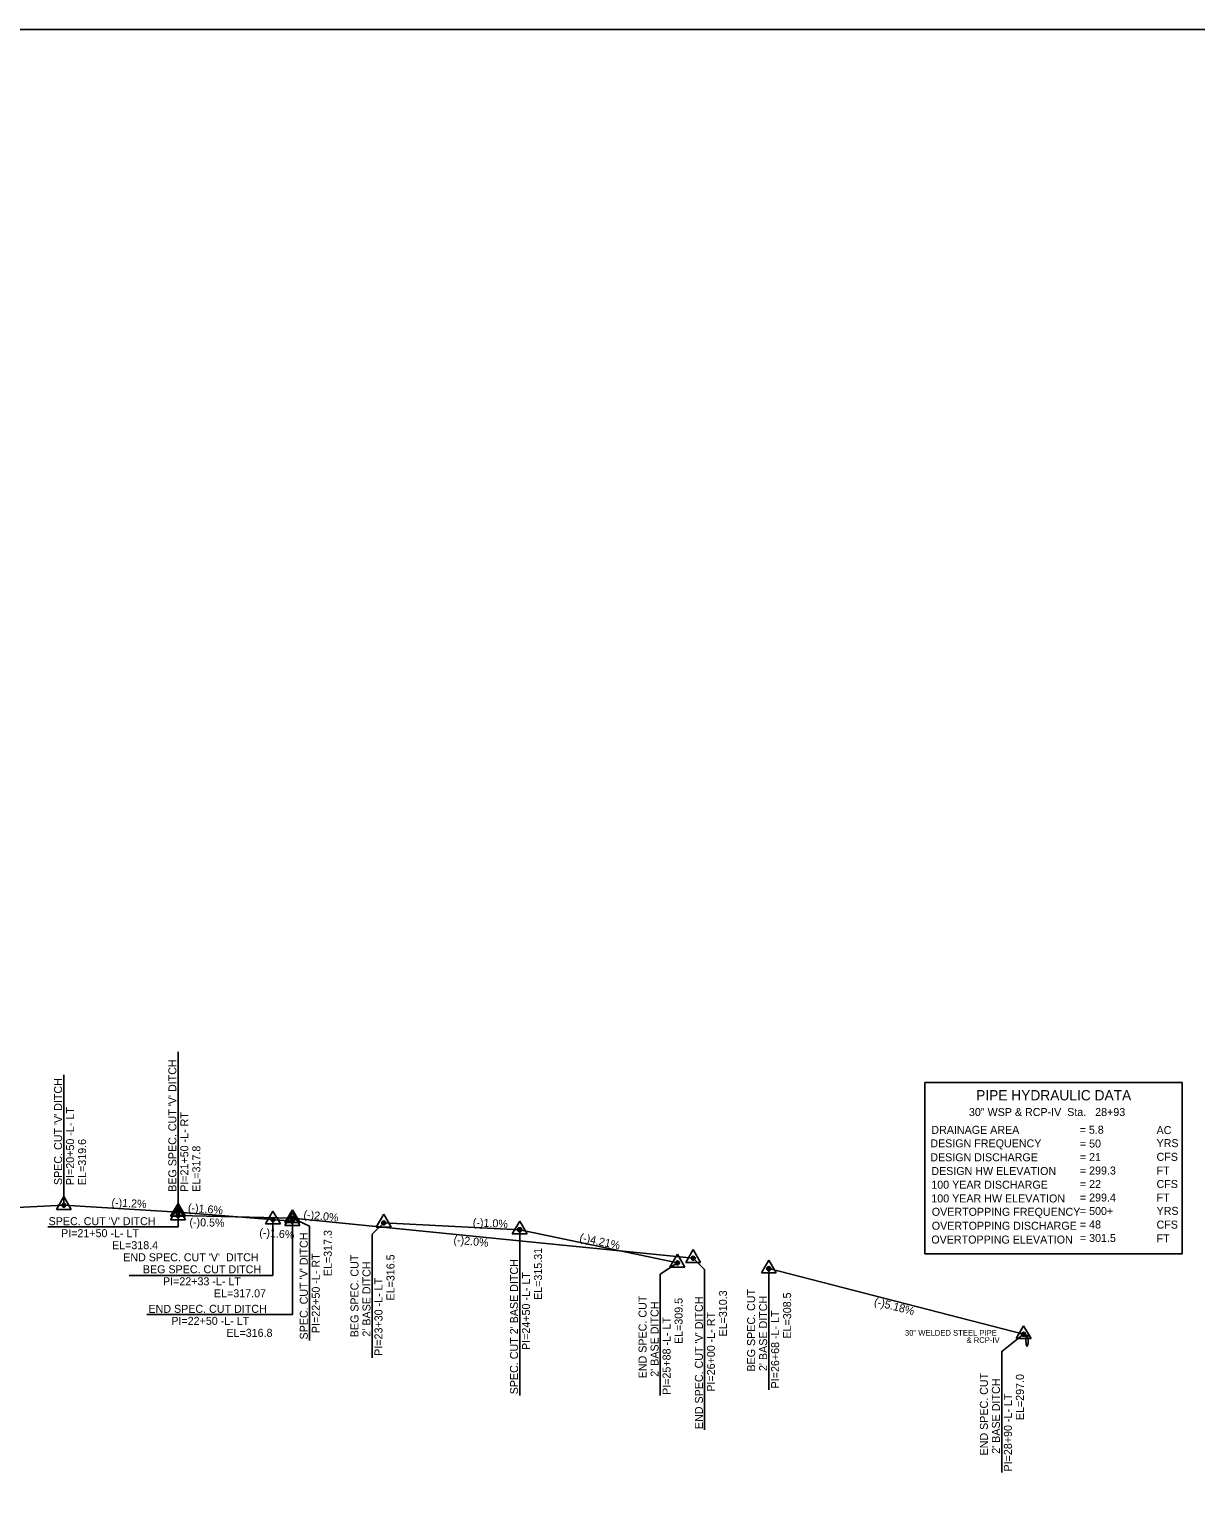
# Model space of a CAD drawing. Extents: x 2110519 to 2119088, y 667494 to 672447.
# Drawn here: x 2113747 to 2114767, y 671161 to 672447 of the extents above; entities that cross this region are included whole.
import ezdxf

# ---------------------------------------------------------------- set-up
doc = ezdxf.new("R2010")
doc.units = 0
for name, color, linetype in [('Exist Horizontal Alignment', 7, 'Continuous'), ('Old_Level_1', 7, 'Continuous'), ('Old_Level_2', 7, 'Continuous'), ('Prop Conc 1ft 6in Curb and Gutter', 7, 'Continuous'), ('Prop Conc 5in Monolithic Surface Mount Island', 7, 'Continuous'), ('Prop Conc Curb 8in x 18in', 7, 'Continuous'), ('Prop EOT', 7, 'Continuous'), ('Prop Paved Shoulder', 7, 'Continuous'), ('Scratch_Level_4', 7, 'Continuous')]:
    doc.layers.add(name, color=color, linetype=linetype)

msp = doc.modelspace()

# ---------------------------------------------------------------- linework, layer by layer
at = {"layer": 'Exist Horizontal Alignment'}
msp.add_lwpolyline([(2110519.2, 672447), (2115845.7, 672447), (2115845.7, 670168.2), (2110519.2, 670168.2)], close=True, dxfattribs=at)
at = {"layer": 'Old_Level_1'}
for p, q in [((2113776.7, 671425.7), (2113770.2, 671414.5)), ((2113776.7, 671425.7), (2113783.2, 671414.5)), ((2113876.7, 671419.7), (2113870.2, 671408.5)), ((2113876.7, 671419.7), (2113883.2, 671408.5)), ((2113770.2, 671414.5), (2113783.2, 671414.5)), ((2113870.2, 671408.5), (2113883.2, 671408.5)), ((2113959.7, 671413.1), (2113953.2, 671401.9)), ((2113959.7, 671413.1), (2113966.2, 671401.9)), ((2113959.7, 671356.7), (2113959.7, 671405.6)), ((2113976.7, 671411.7), (2113970.2, 671400.5)), ((2113976.7, 671411.7), (2113983.2, 671400.5)), ((2114056.7, 671410.2), (2114050.2, 671399)), ((2114056.7, 671410.2), (2114063.2, 671399)), ((2114175.7, 671404.2), (2114169.2, 671393)), ((2114175.7, 671404.2), (2114182.2, 671393)), ((2113953.2, 671401.9), (2113966.2, 671401.9)), ((2113970.2, 671400.5), (2113983.2, 671400.5)), ((2114050.2, 671399), (2114063.2, 671399)), ((2114169.2, 671393), (2114182.2, 671393)), ((2114175.7, 671396.7), (2114175.7, 671251.7)), ((2114313.7, 671375.2), (2114307.2, 671364)), ((2114307.2, 671364), (2114320.2, 671364)), ((2114313.7, 671375.2), (2114320.2, 671364)), ((2114393.7, 671370.2), (2114387.2, 671359)), ((2114393.7, 671370.2), (2114400.2, 671359)), ((2113833.9, 671356.7), (2113959.7, 671356.7)), ((2114387.2, 671359), (2114400.2, 671359)), ((2114393.7, 671362.7), (2114393.7, 671256.7)), ((2114616.7, 671312.7), (2114610.2, 671301.5)), ((2114616.7, 671312.7), (2114623.2, 671301.5)), ((2114610.2, 671301.5), (2114623.2, 671301.5))]:
    msp.add_line(p, q, dxfattribs=at)
for points in [[(2113776.7, 671418.2), (2113776.7, 671532.2)], [(2113876.7, 671412.2), (2113876.7, 671399.2), (2113762.7, 671399.2)], [(2113976.7, 671404.2), (2113976.7, 671322.5), (2113849.3, 671322.5)], [(2114056.7, 671402.7), (2114046.7, 671392.7), (2114046.7, 671284.7)], [(2114313.7, 671367.7), (2114298.7, 671357.7), (2114298.7, 671251.7)], [(2114616.7, 671305.2), (2114597.6, 671290.2), (2114597.6, 671184.2)]]:
    msp.add_lwpolyline(points, dxfattribs=at)
for centre, radius in [((2113776.7, 671418.2), 1.75), ((2113776.7, 671418.2), 1.2), ((2113776.7, 671418.2), 0.5), ((2113876.7, 671412.2), 1.75), ((2113876.7, 671412.2), 1.2), ((2113876.7, 671412.2), 0.5), ((2113959.7, 671405.6), 1.75), ((2113959.7, 671405.6), 1.2), ((2113959.7, 671405.6), 0.5), ((2113976.7, 671404.2), 1.75), ((2113976.7, 671404.2), 1.2), ((2113976.7, 671404.2), 0.5), ((2114056.7, 671402.7), 1.75), ((2114056.7, 671402.7), 1.2), ((2114056.7, 671402.7), 0.5), ((2114175.7, 671396.7), 1.75), ((2114175.7, 671396.7), 1.2), ((2114175.7, 671396.7), 0.5), ((2114313.7, 671367.7), 1.75), ((2114313.7, 671367.7), 1.2), ((2114313.7, 671367.7), 0.5), ((2114393.7, 671362.7), 1.75), ((2114393.7, 671362.7), 1.2), ((2114393.7, 671362.7), 0.5), ((2114616.7, 671305.2), 1.75), ((2114616.7, 671305.2), 1.2), ((2114616.7, 671305.2), 0.5)]:
    msp.add_circle(centre, radius, dxfattribs=at)
at = {"layer": 'Old_Level_2'}
for p, q in [((2113626.7, 671410.7), (2113776.7, 671418.2)), ((2114393.7, 671362.7), (2114616.7, 671305.2)), ((2114616.7, 671305.2), (2114616.7, 671305.2))]:
    msp.add_line(p, q, dxfattribs=at)
for points in [[(2113776.7, 671418.2), (2113876.7, 671412.2), (2113976.7, 671404.2)], [(2114056.7, 671402.7), (2114175.7, 671396.7), (2114313.7, 671367.7)]]:
    msp.add_lwpolyline(points, dxfattribs=at)
at = {"layer": 'Prop Conc Curb 8in x 18in'}
msp.add_lwpolyline([(2114530.3, 671375.5), (2114755.3, 671375.5), (2114755.3, 671525.5), (2114530.3, 671525.5)], close=True, dxfattribs=at)
at = {"layer": 'Prop EOT'}
msp.add_lwpolyline([(2113876.7, 671409.2), (2113976.7, 671406.7), (2114327.5, 671371.8)], dxfattribs=at)
at = {"layer": 'Prop Paved Shoulder'}
msp.add_ellipse((2114619.7, 671299.7), major_axis=(0, 5), ratio=0.2, dxfattribs=at)
at = {"layer": 'Scratch_Level_4'}
for p, q in [((2113876.7, 671409.2), (2113876.7, 671552.3)), ((2113876.7, 671416.7), (2113870.2, 671405.5)), ((2113876.7, 671416.7), (2113883.2, 671405.5)), ((2113870.2, 671405.5), (2113883.2, 671405.5)), ((2113976.7, 671414.2), (2113970.2, 671403)), ((2113970.2, 671403), (2113983.2, 671403)), ((2113976.7, 671414.2), (2113983.2, 671403)), ((2114327.5, 671379.3), (2114321, 671368.1)), ((2114327.5, 671379.3), (2114334, 671368.1)), ((2114321, 671368.1), (2114334, 671368.1))]:
    msp.add_line(p, q, dxfattribs=at)
for points in [[(2113976.7, 671406.7), (2113991.7, 671399.8), (2113991.7, 671299.8)], [(2114327.5, 671371.8), (2114337.5, 671361.8), (2114337.5, 671221.7)]]:
    msp.add_lwpolyline(points, dxfattribs=at)
for centre, radius in [((2113876.7, 671409.2), 1.75), ((2113876.7, 671409.2), 1.2), ((2113876.7, 671409.2), 0.5), ((2113976.7, 671406.7), 1.75), ((2113976.7, 671406.7), 1.2), ((2113976.7, 671406.7), 0.5), ((2114327.5, 671371.8), 1.75), ((2114327.5, 671371.8), 1.2), ((2114327.5, 671371.8), 0.5)]:
    msp.add_circle(centre, radius, dxfattribs=at)

# ---------------------------------------------------------------- texts
at = {"layer": 'Old_Level_1'}
for s, rotation, p in [("SPEC. CUT 'V' DITCH ", 90, (2113775.2, 671435.8)), ('PI=20+50 -L- LT', 90, (2113785.7, 671435.8)), ('EL=319.6', 90, (2113796.2, 671435.8)), ('(-)1.6%', 355.4261, (2113885.1, 671412.6)), ("SPEC. CUT 'V' DITCH ", 0, (2113763.4, 671400.7)), ('PI=21+50 -L- LT', 0, (2113774.3, 671390.2)), ('(-)1.6%', 355.4261, (2113947.6, 671391.1)), ('EL=318.4', 0, (2113818.9, 671379.7)), ('EL=315.31', 90, (2114195.2, 671335.3)), ("END SPEC. CUT 'V'  DITCH", 0, (2113828.7, 671369.1)), ('BEG SPEC. CUT DITCH ', 0, (2113845.9, 671358.6)), ('BEG SPEC. CUT ', 90, (2114034.6, 671302.6)), ("2' BASE DITCH ", 90, (2114045.1, 671303.2)), ('EL=316.5', 90, (2114066.1, 671334.8)), ("SPEC. CUT 2' BASE DITCH ", 90, (2114174.2, 671252.7)), ('PI=22+33 -L- LT', 0, (2113863.5, 671348.1)), ('PI=23+30 -L- LT', 90, (2114055.6, 671286.4)), ('PI=24+50 -L- LT', 90, (2114184.7, 671291.5)), ('EL=317.07', 0, (2113908.1, 671337.6)), ('END SPEC. CUT ', 90, (2114286.7, 671266.7)), ('BEG SPEC. CUT ', 90, (2114381.7, 671272.6)), ('EL=308.5', 90, (2114413.2, 671301.5)), ('END SPEC. CUT DITCH ', 0, (2113850.8, 671324)), ("2' BASE DITCH ", 90, (2114297.2, 671268.1)), ('EL=309.5', 90, (2114318.2, 671296.7)), ("2' BASE DITCH ", 90, (2114392.2, 671273.1)), ('PI=26+68 -L- LT', 90, (2114402.7, 671257.9)), ('PI=22+50 -L- LT', 0, (2113870.8, 671313.5)), ('PI=25+88 -L- LT', 90, (2114307.7, 671252.2)), ('EL=316.8', 0, (2113919, 671303)), ('END SPEC. CUT ', 90, (2114585.4, 671199.2)), ("2' BASE DITCH", 90, (2114595.9, 671200.7)), ('EL=297.0', 90, (2114616.9, 671230.1)), ('PI=28+90 -L- LT', 90, (2114606.4, 671185.2))]:
    msp.add_text(s, height=7, rotation=rotation, dxfattribs=at).set_placement(p)
at = {"layer": 'Old_Level_2'}
for s, rotation, p in [('(-)1.2%', 357.1369, (2113818.3, 671417.2)), ('(-)1.0%', 357.1136, (2114134.5, 671399.8)), ('(-)4.21%', 348.1124, (2114227.6, 671386.8)), ('(-)5.18%', 345.5534, (2114485.3, 671330.8))]:
    msp.add_text(s, height=7, rotation=rotation, dxfattribs=at).set_placement(p)
at = {"layer": 'Prop Conc 1ft 6in Curb and Gutter'}
for s, height, p in [('PIPE HYDRAULIC DATA', 9, (2114575.1, 671509.9)), ('30" WSP & RCP-IV  Sta.   28+93   ', 7, (2114568.8, 671496.2)), ('DRAINAGE AREA', 7, (2114535.9, 671480.6)), ('= 5.8    ', 7, (2114665.7, 671480.7)), ('AC', 7, (2114733, 671480.4)), ('DESIGN FREQUENCY', 7, (2114535, 671468.8)), ('= 50 ', 7, (2114665.9, 671468.6)), ('YRS', 7, (2114733, 671469)), ('DESIGN DISCHARGE', 7, (2114535, 671456.6)), ('= 21      ', 7, (2114665.9, 671456.8)), ('CFS', 7, (2114733, 671457)), ('DESIGN HW ELEVATION', 7, (2114535.9, 671444.6)), ('= 299.3   ', 7, (2114665.9, 671445)), ('FT', 7, (2114733, 671445)), ('100 YEAR DISCHARGE', 7, (2114535.9, 671432.6)), ('= 22      ', 7, (2114665.9, 671433.2)), ('= 299.4   ', 7, (2114665.9, 671421.4)), ('CFS', 7, (2114733, 671433.2)), ('FT', 7, (2114733, 671421.4)), ('100 YEAR HW ELEVATION', 7, (2114535.9, 671420.6)), ('OVERTOPPING FREQUENCY', 7, (2114536.3, 671408.9)), ('= 500+  ', 7, (2114665.9, 671409.6)), ('YRS', 7, (2114733, 671409.7)), ('OVERTOPPING DISCHARGE', 7, (2114536.3, 671396.7)), ('= 48      ', 7, (2114665.9, 671397.8)), ('CFS', 7, (2114733, 671397.7)), ('OVERTOPPING ELEVATION', 7, (2114535.9, 671384.6)), ('= 301.5   ', 7, (2114665.9, 671386)), ('FT', 7, (2114733, 671385.6))]:
    msp.add_text(s, height=height, dxfattribs=at).set_placement(p)
at = {"layer": 'Prop Conc 5in Monolithic Surface Mount Island'}
for s, p in [('30" WELDED STEEL PIPE', (2114512.8, 671304)), ('& RCP-IV', (2114566.7, 671297.7))]:
    msp.add_text(s, height=5, dxfattribs=at).set_placement(p)
at = {"layer": 'Scratch_Level_4'}
for s, rotation, p in [("BEG SPEC. CUT 'V' DITCH ", 90, (2113875.2, 671429.9)), ('PI=21+50 -L- RT', 90, (2113885.7, 671429.9)), ('EL=317.8', 90, (2113896.2, 671429.9)), ('(-)0.5%', 358.5679, (2113886.6, 671400)), ('(-)2.0%', 354.3081, (2113986.2, 671406.8)), ("SPEC. CUT 'V' DITCH ", 90, (2113990.2, 671300.7)), ('EL=317.3', 90, (2114011.2, 671356.1)), ('(-)2.0%', 354.3081, (2114117.5, 671384.7)), ('PI=22+50 -L- RT', 90, (2114000.7, 671306.3)), ('EL=310.3', 90, (2114357, 671303.3)), ("END SPEC. CUT 'V' DITCH ", 90, (2114336, 671222.3)), ('PI=26+00 -L- RT', 90, (2114346.5, 671255))]:
    msp.add_text(s, height=7, rotation=rotation, dxfattribs=at).set_placement(p)

doc.saveas('drawing.dxf')
